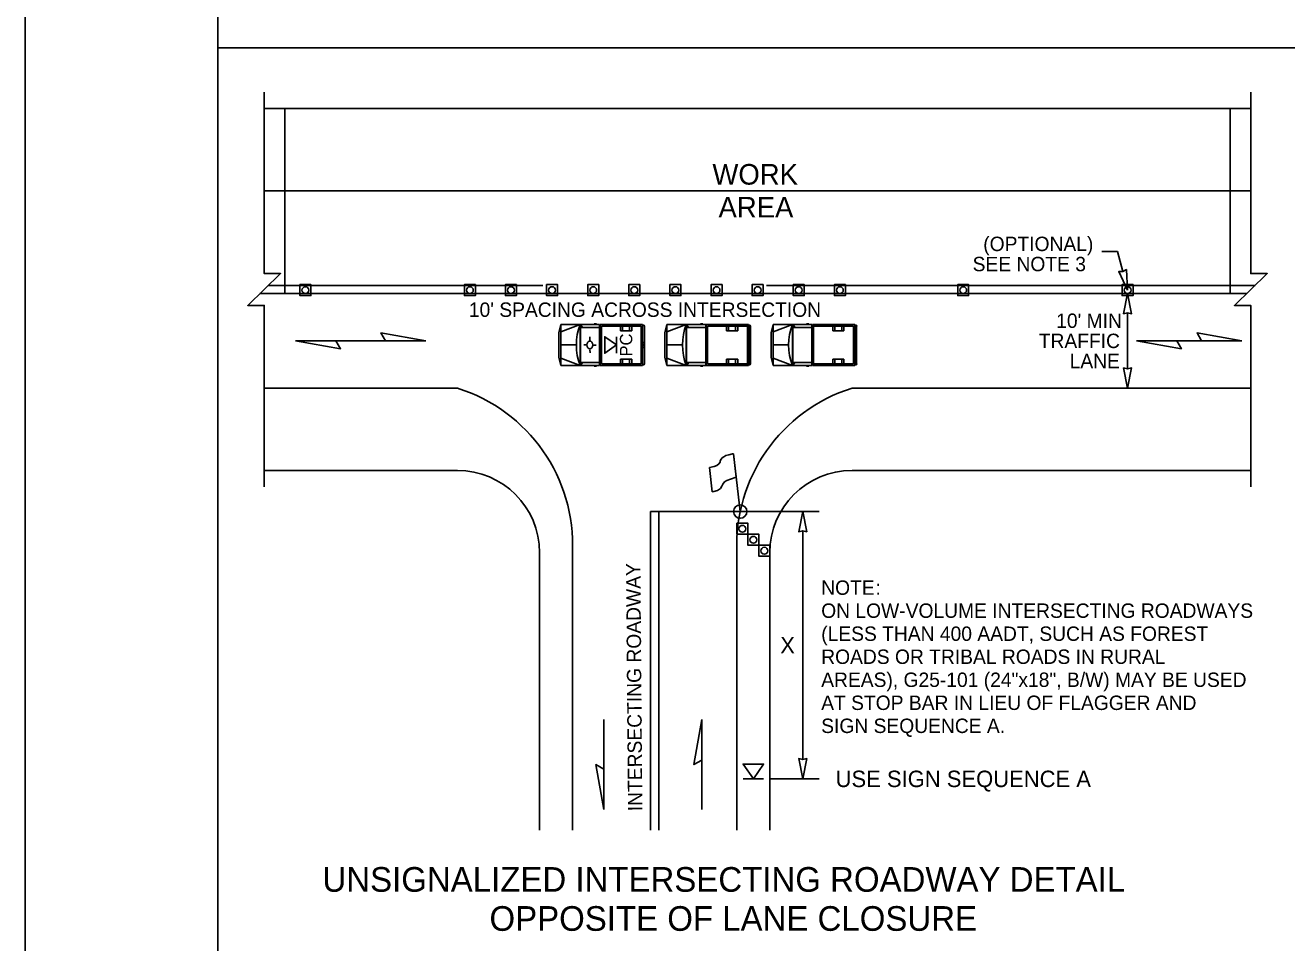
# Model space of a CAD drawing. Extents: x 99999.1 to 100095.7, y 99995 to 100010.7.
# Drawn here: x 100019.06 to 100025.2, y 100001.63 to 100006.09 of the extents above; entities that cross this region are included whole.
import ezdxf

# ---------------------------------------------------------------- set-up
doc = ezdxf.new("R2010")
doc.units = 0
for name, color, linetype in [('RD_ED_ShoulderPavedEdge', 7, 'Continuous'), ('RD_MK_LineDblYellowCenter', 7, 'Continuous'), ('RD_MK_LineEdgeWhite', 7, 'Continuous'), ('RD_MK_LineStop', 7, 'Continuous'), ('SH_DE_DetailBody1Text', 7, 'Continuous'), ('SH_DE_DetailHeading2Text', 7, 'Continuous'), ('SH_GI_PlotLimits', 7, 'Continuous'), ('SH_GI_SheetBorder', 7, 'Continuous'), ('TR_WZ_FlaggingStation', 7, 'Continuous'), ('TR_WZ_MotoristVehicle', 7, 'Continuous'), ('TR_WZ_PortableSignMountBlk-Org', 7, 'Continuous'), ('TR_WZ_PortableSignMountBlk-Wht', 7, 'Continuous'), ('TR_WZ_TrafficCone', 7, 'Continuous'), ('TR_WZ_WorkAreaLabel', 7, 'Continuous'), ('TR_WZ_WorkZoneDetails', 7, 'Continuous'), ('TR_WZ_WorkZoneTextCurrent', 7, 'Continuous')]:
    doc.layers.add(name, color=color, linetype=linetype)

msp = doc.modelspace()

# ---------------------------------------------------------------- linework, layer by layer
at = {"layer": 'RD_ED_ShoulderPavedEdge'}
for p, q in [((100020.225, 100005.6849), (100025.025, 100005.6849)), ((100020.225, 100003.9249), (100021.165, 100003.9249)), ((100023.085, 100003.9249), (100025.025, 100003.9249))]:
    msp.add_line(p, q, dxfattribs=at)
for points in [[(100021.565, 100002.1759), (100021.565, 100003.5249)], [(100022.685, 100002.1759), (100022.685, 100003.5249)]]:
    msp.add_lwpolyline(points, dxfattribs=at)
for centre, start, end in [((100021.165, 100003.5249), 0, 90), ((100023.085, 100003.5249), 90, 180)]:
    msp.add_arc(centre, 0.4, start, end, dxfattribs=at)
at = {"layer": 'RD_MK_LineDblYellowCenter'}
for p, q in [((100020.2457, 100004.8249), (100021.5812, 100004.8249)), ((100022.6688, 100004.8249), (100025.0457, 100004.8249)), ((100020.2043, 100004.7849), (100021.5812, 100004.7849)), ((100022.6688, 100004.7849), (100025.0043, 100004.7849)), ((100022.105, 100002.1759), (100022.105, 100003.7249)), ((100022.145, 100002.1759), (100022.145, 100003.7249))]:
    msp.add_line(p, q, dxfattribs=at)
at = {"layer": 'RD_MK_LineEdgeWhite'}
for p, q in [((100020.225, 100005.2849), (100025.025, 100005.2849)), ((100020.225, 100004.3249), (100021.165, 100004.3249)), ((100023.085, 100004.3249), (100025.025, 100004.3249)), ((100021.725, 100003.5249), (100021.725, 100002.1759)), ((100022.525, 100003.5249), (100022.525, 100002.1759))]:
    msp.add_line(p, q, dxfattribs=at)
for centre, start, end in [((100020.9258, 100003.5615), 357.37881, 72.60523), ((100023.3242, 100003.5615), 107.39477, 182.62119)]:
    msp.add_arc(centre, 0.8, start, end, dxfattribs=at)
at = {"layer": 'RD_MK_LineStop'}
msp.add_line((100022.541, 100003.7249), (100022.105, 100003.7249), dxfattribs=at)
at = {"layer": 'SH_GI_PlotLimits'}
msp.add_lwpolyline([(100019.0625, 99999.6875), (100036.0625, 99999.6875), (100036.0625, 100010.6875), (100019.0625, 100010.6875)], close=True, dxfattribs=at)
at = {"layer": 'SH_GI_SheetBorder'}
msp.add_line((100020, 100010.375), (100020, 100000), dxfattribs=at)
at = {"layer": 'TR_WZ_FlaggingStation'}
for p, q in [((100022.522, 100003.8918), (100022.5089, 100004.0062)), ((100022.541, 100003.7249), (100022.509, 100004.0059)), ((100022.391, 100003.9384), (100022.4043, 100003.8212)), ((100022.522, 100003.8918), (100022.522, 100003.8918))]:
    msp.add_line(p, q, dxfattribs=at)
for points in [[(100022.5089, 100004.0062), (100022.5032, 100004.0049), (100022.4854, 100004.0015), (100022.4715, 100003.9973), (100022.4619, 100003.9912), (100022.4533, 100003.9865), (100022.4477, 100003.9797), (100022.4434, 100003.9718), (100022.4429, 100003.9656), (100022.4375, 100003.9564), (100022.4267, 100003.949), (100022.4143, 100003.9438), (100022.391, 100003.9384)], [(100022.4043, 100003.8212), (100022.4124, 100003.8226), (100022.4301, 100003.8272), (100022.4458, 100003.8377), (100022.4523, 100003.8483), (100022.4562, 100003.8586), (100022.4653, 100003.8695), (100022.4763, 100003.8757), (100022.4936, 100003.8828), (100022.522, 100003.8918)]]:
    msp.add_lwpolyline(points, dxfattribs=at)
msp.add_circle((100022.541, 100003.7249), 0.0325, dxfattribs=at)
at = {"layer": 'TR_WZ_MotoristVehicle'}
for p, q in [((100021.668, 100004.6349), (100021.6587, 100004.5946)), ((100021.668, 100004.6349), (100021.668, 100004.4349)), ((100021.668, 100004.6349), (100021.8569, 100004.6349)), ((100021.668, 100004.5983), (100021.7625, 100004.6349)), ((100021.7625, 100004.6349), (100021.7625, 100004.4349)), ((100021.7642, 100004.6349), (100021.7642, 100004.4349)), ((100021.7642, 100004.6349), (100021.7762, 100004.6194)), ((100021.7642, 100004.6194), (100021.8569, 100004.6194)), ((100021.8311, 100004.6377), (100021.8425, 100004.6377)), ((100021.8569, 100004.6349), (100021.8569, 100004.4349)), ((100022.0654, 100004.6349), (100021.8597, 100004.6349)), ((100021.8597, 100004.6349), (100021.8597, 100004.4349)), ((100022.0595, 100004.6269), (100021.8655, 100004.6269)), ((100021.8655, 100004.6269), (100021.8655, 100004.4429)), ((100021.9582, 100004.6269), (100021.9582, 100004.6039)), ((100021.9682, 100004.6269), (100021.9682, 100004.6039)), ((100022.0022, 100004.6269), (100022.0022, 100004.6039)), ((100022.0132, 100004.6269), (100022.0132, 100004.6039)), ((100022.0595, 100004.6269), (100022.0595, 100004.4429)), ((100022.0654, 100004.6349), (100022.0654, 100004.4349)), ((100022.0705, 100004.6316), (100022.0661, 100004.6316)), ((100022.0661, 100004.6316), (100022.0661, 100004.4382)), ((100022.075, 100004.6255), (100022.075, 100004.4443)), ((100022.1843, 100004.6349), (100022.175, 100004.5946)), ((100022.1843, 100004.6349), (100022.1843, 100004.4349)), ((100022.1843, 100004.6349), (100022.3732, 100004.6349)), ((100022.1843, 100004.5983), (100022.2787, 100004.6349)), ((100022.2787, 100004.6349), (100022.2787, 100004.4349)), ((100022.2804, 100004.6349), (100022.2804, 100004.4349)), ((100022.2804, 100004.6349), (100022.2925, 100004.6194)), ((100022.2804, 100004.6194), (100022.3732, 100004.6194)), ((100022.3474, 100004.6377), (100022.3587, 100004.6377)), ((100022.3732, 100004.6349), (100022.3732, 100004.4349)), ((100022.5816, 100004.6349), (100022.3759, 100004.6349)), ((100022.3759, 100004.6349), (100022.3759, 100004.4349)), ((100022.5758, 100004.6269), (100022.3818, 100004.6269)), ((100022.3818, 100004.6269), (100022.3818, 100004.4429)), ((100022.4745, 100004.6269), (100022.4745, 100004.6039)), ((100022.4844, 100004.6269), (100022.4844, 100004.6039)), ((100022.5185, 100004.6269), (100022.5185, 100004.6039)), ((100022.5294, 100004.6269), (100022.5294, 100004.6039)), ((100022.5758, 100004.6269), (100022.5758, 100004.4429)), ((100022.5816, 100004.6349), (100022.5816, 100004.4349)), ((100022.5868, 100004.6316), (100022.5823, 100004.6316)), ((100022.5823, 100004.6316), (100022.5823, 100004.4382)), ((100022.5913, 100004.6255), (100022.5913, 100004.4443)), ((100022.7005, 100004.6349), (100022.6913, 100004.5946)), ((100022.7005, 100004.6349), (100022.7005, 100004.4349)), ((100022.7005, 100004.6349), (100022.8894, 100004.6349)), ((100022.7005, 100004.5983), (100022.795, 100004.6349)), ((100022.795, 100004.6349), (100022.795, 100004.4349)), ((100022.7967, 100004.6349), (100022.7967, 100004.4349)), ((100022.7967, 100004.6349), (100022.8087, 100004.6194)), ((100022.7967, 100004.6194), (100022.8894, 100004.6194)), ((100022.8637, 100004.6377), (100022.875, 100004.6377)), ((100022.8894, 100004.6349), (100022.8894, 100004.4349)), ((100023.0979, 100004.6349), (100022.8922, 100004.6349)), ((100022.8922, 100004.6349), (100022.8922, 100004.4349)), ((100023.0921, 100004.6269), (100022.898, 100004.6269)), ((100022.898, 100004.6269), (100022.898, 100004.4429)), ((100022.9908, 100004.6269), (100022.9908, 100004.6039)), ((100023.0007, 100004.6269), (100023.0007, 100004.6039)), ((100023.0347, 100004.6269), (100023.0347, 100004.6039)), ((100023.0457, 100004.6269), (100023.0457, 100004.6039)), ((100023.0921, 100004.6269), (100023.0921, 100004.4429)), ((100023.0979, 100004.6349), (100023.0979, 100004.4349)), ((100023.1031, 100004.6316), (100023.0986, 100004.6316)), ((100023.0986, 100004.6316), (100023.0986, 100004.4382)), ((100023.1075, 100004.6255), (100023.1075, 100004.4443)), ((100021.6587, 100004.5946), (100021.6587, 100004.4753)), ((100021.8095, 100004.5746), (100021.8095, 100004.5584)), ((100022.0132, 100004.6039), (100021.9582, 100004.6039)), ((100022.075, 100004.549), (100022.0661, 100004.5453)), ((100022.175, 100004.5946), (100022.175, 100004.4753)), ((100022.5294, 100004.6039), (100022.4745, 100004.6039)), ((100022.5913, 100004.549), (100022.5823, 100004.5453)), ((100022.6913, 100004.5946), (100022.6913, 100004.4753)), ((100023.0457, 100004.6039), (100022.9908, 100004.6039)), ((100023.1075, 100004.549), (100023.0986, 100004.5453)), ((100021.668, 100004.5349), (100021.7439, 100004.5349)), ((100021.7794, 100004.5351), (100021.792, 100004.535)), ((100021.8102, 100004.4965), (100021.8099, 100004.5115)), ((100021.8236, 100004.5346), (100021.8236, 100004.5346)), ((100021.8404, 100004.5342), (100021.8255, 100004.5345)), ((100022.075, 100004.5208), (100022.0661, 100004.5246)), ((100022.0726, 100004.5349), (100022.0685, 100004.5349)), ((100022.0705, 100004.5377), (100022.0705, 100004.5321)), ((100022.1843, 100004.5349), (100022.2602, 100004.5349)), ((100022.5913, 100004.5208), (100022.5823, 100004.5246)), ((100022.5889, 100004.5349), (100022.5847, 100004.5349)), ((100022.5868, 100004.5377), (100022.5868, 100004.5321)), ((100022.7005, 100004.5349), (100022.7764, 100004.5349)), ((100023.1075, 100004.5208), (100023.0986, 100004.5246)), ((100023.1051, 100004.5349), (100023.101, 100004.5349)), ((100023.1031, 100004.5377), (100023.1031, 100004.5321)), ((100021.668, 100004.4349), (100021.6587, 100004.4753)), ((100021.668, 100004.4716), (100021.7625, 100004.4349)), ((100021.668, 100004.4349), (100021.8569, 100004.4349)), ((100021.7642, 100004.4504), (100021.8569, 100004.4504)), ((100021.7741, 100004.4504), (100021.7642, 100004.4349)), ((100021.8311, 100004.4321), (100021.8425, 100004.4321)), ((100022.0654, 100004.4349), (100021.8597, 100004.4349)), ((100022.0595, 100004.4429), (100021.8655, 100004.4429)), ((100021.9582, 100004.4429), (100021.9582, 100004.4659)), ((100022.0132, 100004.4659), (100021.9582, 100004.4659)), ((100021.9682, 100004.4429), (100021.9682, 100004.4659)), ((100022.0022, 100004.4429), (100022.0022, 100004.4659)), ((100022.0132, 100004.4429), (100022.0132, 100004.4659)), ((100022.0705, 100004.4382), (100022.0661, 100004.4382)), ((100022.1843, 100004.4349), (100022.175, 100004.4753)), ((100022.1843, 100004.4716), (100022.2787, 100004.4349)), ((100022.1843, 100004.4349), (100022.3732, 100004.4349)), ((100022.2804, 100004.4504), (100022.3732, 100004.4504)), ((100022.2904, 100004.4504), (100022.2804, 100004.4349)), ((100022.3474, 100004.4321), (100022.3587, 100004.4321)), ((100022.5816, 100004.4349), (100022.3759, 100004.4349)), ((100022.5758, 100004.4429), (100022.3818, 100004.4429)), ((100022.4745, 100004.4429), (100022.4745, 100004.4659)), ((100022.5294, 100004.4659), (100022.4745, 100004.4659)), ((100022.4844, 100004.4429), (100022.4844, 100004.4659)), ((100022.5185, 100004.4429), (100022.5185, 100004.4659)), ((100022.5294, 100004.4429), (100022.5294, 100004.4659)), ((100022.5868, 100004.4382), (100022.5823, 100004.4382)), ((100022.7005, 100004.4349), (100022.6913, 100004.4753)), ((100022.7005, 100004.4716), (100022.795, 100004.4349)), ((100022.7005, 100004.4349), (100022.8894, 100004.4349)), ((100022.7967, 100004.4504), (100022.8894, 100004.4504)), ((100022.8067, 100004.4504), (100022.7967, 100004.4349)), ((100022.8637, 100004.4321), (100022.875, 100004.4321)), ((100023.0979, 100004.4349), (100022.8922, 100004.4349)), ((100023.0921, 100004.4429), (100022.898, 100004.4429)), ((100022.9908, 100004.4429), (100022.9908, 100004.4659)), ((100023.0457, 100004.4659), (100022.9908, 100004.4659)), ((100023.0007, 100004.4429), (100023.0007, 100004.4659)), ((100023.0347, 100004.4429), (100023.0347, 100004.4659)), ((100023.0457, 100004.4429), (100023.0457, 100004.4659)), ((100023.1031, 100004.4382), (100023.0986, 100004.4382))]:
    msp.add_line(p, q, dxfattribs=at)
for centre, major_axis, start_param, end_param in [((100021.8974, 100004.5349), (0, -0.2099), 4.215667, 5.208926), ((100022.0705, 100004.6255), (0, 0.0061), 4.712389, 6.283185), ((100022.4137, 100004.5349), (0, -0.2099), 4.215667, 5.208926), ((100022.5868, 100004.6255), (0, 0.0061), 4.712389, 6.283185), ((100022.93, 100004.5349), (0, -0.2099), 4.215667, 5.208926), ((100023.1031, 100004.6255), (0, 0.0061), 4.712389, 6.283185), ((100022.0705, 100004.4443), (0, -0.0061), 0, 1.570796), ((100022.5868, 100004.4443), (0, -0.0061), 0, 1.570796), ((100023.1031, 100004.4443), (0, -0.0061), 0, 1.570796)]:
    msp.add_ellipse(centre, major_axis=major_axis, ratio=0.73155, start_param=start_param, end_param=end_param, dxfattribs=at)
for centre, major_axis in [((100021.8095, 100004.5349), (0, 0.0193)), ((100022.0705, 100004.5349), (0, 0.00282)), ((100022.5868, 100004.5349), (0, 0.00282)), ((100023.1031, 100004.5349), (0, 0.00282))]:
    msp.add_ellipse(centre, major_axis=major_axis, ratio=0.73155, dxfattribs=at)
at = {"layer": 'TR_WZ_PortableSignMountBlk-Org'}
msp.add_line((100022.655, 100002.4249), (100022.555, 100002.4249), dxfattribs=at)
msp.add_lwpolyline([(100022.605, 100002.4249), (100022.555, 100002.4968), (100022.655, 100002.4968)], close=True, dxfattribs=at)
at = {"layer": 'TR_WZ_PortableSignMountBlk-Wht'}
msp.add_line((100021.9393, 100004.5748), (100021.9393, 100004.4948), dxfattribs=at)
msp.add_lwpolyline([(100021.9393, 100004.5349), (100021.8819, 100004.4948), (100021.8819, 100004.5748)], close=True, dxfattribs=at)
at = {"layer": 'TR_WZ_TrafficCone'}
for points in [[(100020.399, 100004.8283), (100020.4524, 100004.8283), (100020.4524, 100004.7749), (100020.399, 100004.7749), (100020.399, 100004.8283)], [(100020.399, 100004.7749), (100020.4524, 100004.7749), (100020.4524, 100004.8283), (100020.399, 100004.8283), (100020.399, 100004.7749)], [(100021.199, 100004.8283), (100021.2524, 100004.8283), (100021.2524, 100004.7749), (100021.199, 100004.7749), (100021.199, 100004.8283)], [(100021.199, 100004.7749), (100021.2524, 100004.7749), (100021.2524, 100004.8283), (100021.199, 100004.8283), (100021.199, 100004.7749)], [(100021.399, 100004.8283), (100021.4524, 100004.8283), (100021.4524, 100004.7749), (100021.399, 100004.7749), (100021.399, 100004.8283)], [(100021.399, 100004.7749), (100021.4524, 100004.7749), (100021.4524, 100004.8283), (100021.399, 100004.8283), (100021.399, 100004.7749)], [(100021.599, 100004.8283), (100021.6524, 100004.8283), (100021.6524, 100004.7749), (100021.599, 100004.7749), (100021.599, 100004.8283)], [(100021.599, 100004.7749), (100021.6524, 100004.7749), (100021.6524, 100004.8283), (100021.599, 100004.8283), (100021.599, 100004.7749)], [(100021.799, 100004.8283), (100021.8524, 100004.8283), (100021.8524, 100004.7749), (100021.799, 100004.7749), (100021.799, 100004.8283)], [(100021.799, 100004.7749), (100021.8524, 100004.7749), (100021.8524, 100004.8283), (100021.799, 100004.8283), (100021.799, 100004.7749)], [(100021.999, 100004.8283), (100022.0524, 100004.8283), (100022.0524, 100004.7749), (100021.999, 100004.7749), (100021.999, 100004.8283)], [(100021.999, 100004.7749), (100022.0524, 100004.7749), (100022.0524, 100004.8283), (100021.999, 100004.8283), (100021.999, 100004.7749)], [(100022.199, 100004.8283), (100022.2524, 100004.8283), (100022.2524, 100004.7749), (100022.199, 100004.7749), (100022.199, 100004.8283)], [(100022.199, 100004.7749), (100022.2524, 100004.7749), (100022.2524, 100004.8283), (100022.199, 100004.8283), (100022.199, 100004.7749)], [(100022.399, 100004.8283), (100022.4524, 100004.8283), (100022.4524, 100004.7749), (100022.399, 100004.7749), (100022.399, 100004.8283)], [(100022.399, 100004.7749), (100022.4524, 100004.7749), (100022.4524, 100004.8283), (100022.399, 100004.8283), (100022.399, 100004.7749)], [(100022.599, 100004.8283), (100022.6524, 100004.8283), (100022.6524, 100004.7749), (100022.599, 100004.7749), (100022.599, 100004.8283)], [(100022.599, 100004.7749), (100022.6524, 100004.7749), (100022.6524, 100004.8283), (100022.599, 100004.8283), (100022.599, 100004.7749)], [(100022.799, 100004.8283), (100022.8524, 100004.8283), (100022.8524, 100004.7749), (100022.799, 100004.7749), (100022.799, 100004.8283)], [(100022.799, 100004.7749), (100022.8524, 100004.7749), (100022.8524, 100004.8283), (100022.799, 100004.8283), (100022.799, 100004.7749)], [(100022.999, 100004.8283), (100023.0524, 100004.8283), (100023.0524, 100004.7749), (100022.999, 100004.7749), (100022.999, 100004.8283)], [(100022.999, 100004.7749), (100023.0524, 100004.7749), (100023.0524, 100004.8283), (100022.999, 100004.8283), (100022.999, 100004.7749)], [(100023.599, 100004.8283), (100023.6524, 100004.8283), (100023.6524, 100004.7749), (100023.599, 100004.7749), (100023.599, 100004.8283)], [(100023.599, 100004.7749), (100023.6524, 100004.7749), (100023.6524, 100004.8283), (100023.599, 100004.8283), (100023.599, 100004.7749)], [(100024.399, 100004.8283), (100024.4524, 100004.8283), (100024.4524, 100004.7749), (100024.399, 100004.7749), (100024.399, 100004.8283)], [(100024.399, 100004.7749), (100024.4524, 100004.7749), (100024.4524, 100004.8283), (100024.399, 100004.8283), (100024.399, 100004.7749)], [(100022.525, 100003.6142), (100022.525, 100003.6676), (100022.5783, 100003.6676), (100022.5783, 100003.6142), (100022.525, 100003.6142)], [(100022.5783, 100003.6142), (100022.5783, 100003.6676), (100022.525, 100003.6676), (100022.525, 100003.6142), (100022.5783, 100003.6142)], [(100022.5783, 100003.5609), (100022.5783, 100003.6142), (100022.6317, 100003.6142), (100022.6317, 100003.5609), (100022.5783, 100003.5609)], [(100022.6317, 100003.5609), (100022.6317, 100003.6142), (100022.5783, 100003.6142), (100022.5783, 100003.5609), (100022.6317, 100003.5609)], [(100022.6317, 100003.5076), (100022.6317, 100003.5609), (100022.685, 100003.5609), (100022.685, 100003.5076), (100022.6317, 100003.5076)], [(100022.685, 100003.5076), (100022.685, 100003.5609), (100022.6317, 100003.5609), (100022.6317, 100003.5076), (100022.685, 100003.5076)]]:
    msp.add_lwpolyline(points, dxfattribs=at)
for centre in [(100020.4257, 100004.8016), (100021.2257, 100004.8016), (100021.4257, 100004.8016), (100021.6257, 100004.8016), (100021.8257, 100004.8016), (100022.0257, 100004.8016), (100022.2257, 100004.8016), (100022.4257, 100004.8016), (100022.6257, 100004.8016), (100022.8257, 100004.8016), (100023.0257, 100004.8016), (100023.6257, 100004.8016), (100024.4257, 100004.8016), (100022.5517, 100003.6409), (100022.605, 100003.5876), (100022.6583, 100003.5342)]:
    msp.add_circle(centre, 0.0167, dxfattribs=at)
at = {"layer": 'TR_WZ_WorkZoneDetails'}
for p, q in [((100025.25, 100005.9805), (100020, 100005.9805)), ((100024.3007, 100004.9896), (100024.3769, 100004.9896)), ((100024.4022, 100004.8923), (100024.3769, 100004.9896)), ((100024.4256, 100004.4187), (100024.4256, 100004.6912)), ((100020.5744, 100004.5549), (100020.8156, 100004.5549)), ((100020.8156, 100004.5549), (100020.5744, 100004.5549)), ((100024.7856, 100004.5549), (100024.5445, 100004.5549)), ((100024.6651, 100004.5549), (100024.9062, 100004.5549)), ((100022.541, 100003.7249), (100022.925, 100003.7249)), ((100022.845, 100003.6312), (100022.845, 100002.5187)), ((100021.8772, 100002.4718), (100021.8772, 100002.7129)), ((100022.3545, 100002.5164), (100022.3545, 100002.2753)), ((100022.685, 100002.4249), (100022.925, 100002.4249))]:
    msp.add_line(p, q, dxfattribs=at)
for points in [[(100020.225, 100003.8449), (100020.225, 100004.7275), (100020.145, 100004.7275), (100020.305, 100004.8824), (100020.225, 100004.8824), (100020.225, 100005.7649)], [(100025.025, 100003.8449), (100025.025, 100004.7275), (100024.945, 100004.7275), (100025.105, 100004.8824), (100025.025, 100004.8824), (100025.025, 100005.7649)]]:
    msp.add_lwpolyline(points, dxfattribs=at)
for points in [[(100020.325, 100005.6849), (100020.325, 100004.7849), (100024.925, 100004.7849), (100024.925, 100005.6849)], [(100024.4257, 100004.8016), (100024.3824, 100004.8919), (100024.4022, 100004.8923), (100024.4197, 100004.9016)], [(100024.4257, 100004.7849), (100024.4064, 100004.6866), (100024.4257, 100004.6912), (100024.445, 100004.6866)], [(100020.3779, 100004.5549), (100020.5967, 100004.5164), (100020.5744, 100004.5549)], [(100021.0121, 100004.5549), (100020.7933, 100004.5935), (100020.8156, 100004.5549)], [(100024.4685, 100004.5549), (100024.6873, 100004.5164), (100024.6651, 100004.5549)], [(100024.9821, 100004.5549), (100024.7633, 100004.5935), (100024.7856, 100004.5549)], [(100024.4256, 100004.3249), (100024.4064, 100004.4232), (100024.4256, 100004.4187), (100024.4449, 100004.4232)], [(100022.845, 100003.7249), (100022.8257, 100003.6266), (100022.845, 100003.6312), (100022.8643, 100003.6266)], [(100022.3545, 100002.7129), (100022.316, 100002.4941), (100022.3545, 100002.5164)], [(100022.845, 100002.4249), (100022.8257, 100002.5232), (100022.845, 100002.5187), (100022.8643, 100002.5232)], [(100021.8772, 100002.2753), (100021.8387, 100002.4941), (100021.8772, 100002.4718)]]:
    msp.add_lwpolyline(points, close=True, dxfattribs=at)

# ---------------------------------------------------------------- texts
at = {"layer": 'SH_DE_DetailBody1Text'}
msp.add_text('INTERSECTING ROADWAY', height=0.07, rotation=90.4626, dxfattribs=at).set_placement((100022.0651, 100002.2677))
at = {"layer": 'SH_DE_DetailHeading2Text'}
for s, p in [('UNSIGNALIZED INTERSECTING ROADWAY DETAIL', (100020.5086, 100001.8759)), ('OPPOSITE OF LANE CLOSURE', (100021.3211, 100001.6859))]:
    msp.add_text(s, height=0.12, rotation=360, dxfattribs=at).set_placement(p)
at = {"layer": 'TR_WZ_MotoristVehicle'}
msp.add_text('PC', height=0.06, rotation=90, dxfattribs=at).set_placement((100022.0157, 100004.4789))
at = {"layer": 'TR_WZ_WorkAreaLabel'}
for s, p in [('WORK', (100022.4058, 100005.3149)), ('AREA', (100022.4354, 100005.1549))]:
    msp.add_text(s, height=0.1, dxfattribs=at).set_placement(p)
at = {"layer": 'TR_WZ_WorkZoneDetails'}
for s, p in [('NOTE', (100022.935, 100003.3199)), (':', (100023.1991, 100003.3199)), ('ON LOW-VOLUME INTERSECTING ROADWAYS ', (100022.935, 100003.2079)), ('(LESS THAN 400 AADT, SUCH AS FOREST ', (100022.935, 100003.0959)), ('ROADS OR TRIBAL ROADS IN RURAL ', (100022.935, 100002.9839)), ('AREAS), G25-101 (24"x18", B/W) MAY BE USED ', (100022.935, 100002.8719)), ('AT STOP BAR IN LIEU OF FLAGGER AND ', (100022.935, 100002.7599)), ('SIGN SEQUENCE A.', (100022.935, 100002.6479))]:
    msp.add_text(s, height=0.07, dxfattribs=at).set_placement(p)
at = {"layer": 'TR_WZ_WorkZoneTextCurrent'}
for s, height, p in [('(OPTIONAL)', 0.07, (100023.7233, 100004.9916)), ('SEE NOTE 3', 0.07, (100023.6716, 100004.8936)), ("10' SPACING ACROSS INTERSECTION", 0.07, (100021.2208, 100004.6716)), ("10' MIN", 0.07, (100024.0783, 100004.6179)), ('TRAFFIC', 0.07, (100023.9933, 100004.5199)), ('LANE', 0.07, (100024.1437, 100004.4219)), ('X', 0.08, (100022.7356, 100003.0349)), ('USE SIGN SEQUENCE A', 0.08, (100023.005, 100002.3849))]:
    msp.add_text(s, height=height, dxfattribs=at).set_placement(p)

doc.saveas('drawing.dxf')
